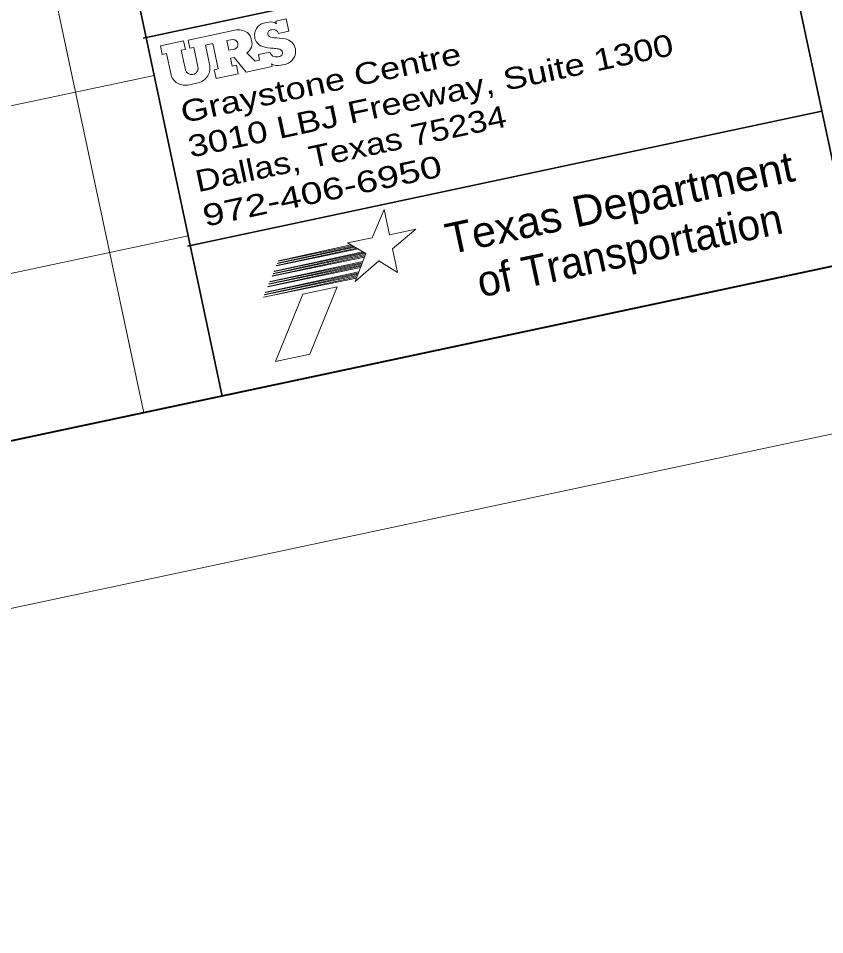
# Model space of a CAD drawing. Extents: x 2357218 to 2371708, y 6973728 to 6980157.
# Drawn here: x 2370463 to 2370955, y 6976249 to 6976808 of the extents above; entities that cross this region are included whole.
import ezdxf
from ezdxf.enums import TextEntityAlignment as Align

# ---------------------------------------------------------------- set-up
doc = ezdxf.new("R2010")
doc.units = 0
doc.header["$LTSCALE"] = 2
doc.layers.add('62', color=7, linetype='Continuous', lineweight=13)
doc.layers.add('63', color=7, linetype='Continuous', lineweight=13)

msp = doc.modelspace()

# ---------------------------------------------------------------- linework, layer by layer
at = {"layer": '62'}
for p, q in [((2370248.639, 6977936.603), (2370539.727, 6976567.134)), ((2370613.117, 6976804.817), (2370616.379, 6976805.51)), ((2370617.969, 6976800.812), (2370617.299, 6976800.67)), ((2370590.421, 6976794.162), (2370594.103, 6976794.945)), ((2370621.607, 6976784.237), (2370622.774, 6976784.526)), ((2370626.668, 6976779.864), (2370623.407, 6976779.171)), ((2370546.085, 6976772.963), (2358711.903, 6974257.531)), ((2370569.722, 6976773.59), (2370570.563, 6976773.769)), ((2370572.972, 6976768.447), (2370567.541, 6976767.296)), ((2370566.878, 6976675.145), (2358732.695, 6974159.712)), ((2371343.073, 6976635.653), (2358039.664, 6973807.926))]:
    msp.add_line(p, q, dxfattribs=at)
at = {"layer": '62', "lineweight": 35}
for p, q in [((2370463.576, 6977161.139), (2370587.67, 6976577.324)), ((2371176.22, 6976931.098), (2370539.396, 6976795.736)), ((2370972.547, 6976661.874), (2370926.598, 6976878.04)), ((2370953.581, 6976751.099), (2370566.378, 6976668.796))]:
    msp.add_line(p, q, dxfattribs=at)
at = {"layer": '62', "lineweight": 40}
msp.add_line((2371224.464, 6976712.679), (2358116.692, 6973926.537), dxfattribs=at)
at = {"layer": '62'}
for points in [[(2370620.492, 6976804.659), (2370620.728, 6976804.709), (2370620.444, 6976806.044), (2370626.757, 6976807.386), (2370628.345, 6976799.913), (2370622.032, 6976798.571)], [(2370572.786, 6976778.312), (2370570.303, 6976789.996), (2370567.988, 6976789.504), (2370566.937, 6976794.451), (2370595.344, 6976800.489)], [(2370556.215, 6976774.02), (2370553.597, 6976786.335), (2370551.072, 6976785.798), (2370549.976, 6976790.956), (2370564.074, 6976793.952), (2370565.17, 6976788.795), (2370562.645, 6976788.258), (2370565.173, 6976776.364)], [(2370617.721, 6976780.053), (2370618.079, 6976778.369), (2370602.298, 6976775.014), (2370594.912, 6976783.895), (2370592.703, 6976783.426), (2370593.732, 6976778.584), (2370596.362, 6976779.143), (2370597.458, 6976773.985), (2370583.886, 6976771.101), (2370582.768, 6976776.363), (2370585.187, 6976776.878), (2370581.899, 6976792.351), (2370577.374, 6976791.389), (2370579.836, 6976779.811)], [(2370594.724, 6976788.916), (2370591.673, 6976788.268), (2370590.421, 6976794.162)], [(2370602.61, 6976786.763), (2370607.807, 6976781.686), (2370610.438, 6976782.245), (2370609.722, 6976785.613), (2370616.666, 6976787.089)]]:
    msp.add_lwpolyline(points, dxfattribs=at)
for points in [[(2370686.385, 6976691.127), (2370679.1, 6976673.906), (2370664.09, 6976670.714), (2370675.305, 6976664.349), (2370668.728, 6976647.259), (2370683.179, 6976659.825), (2370694.543, 6976652.745), (2370691.499, 6976667.061), (2370705.7, 6976679.183), (2370689.65, 6976675.763)], [(2370620.799, 6976656.901), (2370669.709, 6976667.519), (2370670.535, 6976667.045), (2370620.756, 6976656.71)], [(2370621.442, 6976658.465), (2370667.87, 6976668.566), (2370668.711, 6976668.078), (2370621.356, 6976658.278)], [(2370622.034, 6976659.919), (2370666.192, 6976669.507), (2370667.03, 6976669.057), (2370621.977, 6976659.712)], [(2370618.242, 6976650.608), (2370674.752, 6976662.9), (2370674.425, 6976662.064), (2370618.201, 6976650.413)], [(2370618.858, 6976652.171), (2370675.11, 6976664.431), (2370675.293, 6976664.344), (2370675.013, 6976663.626), (2370618.803, 6976651.957)], [(2370619.463, 6976653.612), (2370673.474, 6976665.383), (2370674.411, 6976664.834), (2370619.399, 6976653.407)], [(2370615.598, 6976644.18), (2370672.268, 6976656.479), (2370671.959, 6976655.684), (2370615.537, 6976643.969)], [(2370616.212, 6976645.727), (2370672.865, 6976658.024), (2370672.566, 6976657.24), (2370616.17, 6976645.535)], [(2370616.824, 6976647.168), (2370673.43, 6976659.46), (2370673.119, 6976658.657), (2370616.755, 6976646.979)], [(2370612.966, 6976637.74), (2370669.807, 6976650.091), (2370669.501, 6976649.327), (2370612.885, 6976637.559)], [(2370613.573, 6976639.311), (2370670.412, 6976651.632), (2370670.115, 6976650.883), (2370613.518, 6976639.099)], [(2370614.184, 6976640.73), (2370670.959, 6976653.066), (2370670.66, 6976652.308), (2370614.118, 6976640.534)], [(2370636.881, 6976639.517), (2370620.08, 6976598.402), (2370641.016, 6976602.852), (2370657.803, 6976643.97)]]:
    msp.add_lwpolyline(points, close=True, dxfattribs=at)
for centre, radius, start, end in [((2370597.546, 6976790.537), 10.193, 57.4181, 102.47644), ((2370614.691, 6976797.617), 7.37, 102.32723, 191.15289), ((2370617.472, 6976800.429), 5.198, 54.47521, 102.13887), ((2370618.846, 6976797.598), 3.331, 16.97622, 105.26327), ((2370597.372, 6976793.059), 8.299, 9.96198, 46.96983), ((2370613.981, 6976796.942), 6.564, 186.56461, 251.65547), ((2370617.647, 6976798.529), 2.168, 99.22466, 192.15024), ((2370617.188, 6976798.198), 1.665, 184.31019, 211.43935), ((2370619.351, 6976801.357), 5.392, 228.33024, 267.8676), ((2370604.89, 6976620.593), 175.955, 83.11463, 85.35109), ((2370624.504, 6976787.405), 8.012, 12.4748, 79.35646), ((2370594.147, 6976791.848), 3.097, 3.97357, 90.82265), ((2370594.423, 6976791.733), 2.833, 276.11318, 6.67154), ((2370599.4, 6976792.405), 6.491, 299.63423, 18.78306), ((2370619.226, 6976811.978), 22.489, 251.02735, 268.92656), ((2370620.866, 6976788.659), 4.484, 200.49107, 279.52171), ((2370616.627, 6976761.895), 27.684, 78.98519, 85.48674), ((2370621.85, 6976786.4), 2.67, 8.42761, 88.58816), ((2370622.247, 6976786.709), 2.246, 283.56527, 2.09036), ((2370624.233, 6976787.713), 8.218, 287.23994, 9.97211), ((2370571.011, 6976777.386), 9.152, 282.37291, 15.36393), ((2370621.51, 6976785.711), 6.81, 236.19553, 286.17379), ((2370564.973, 6976775.872), 8.952, 191.94291, 286.66556), ((2370568.864, 6976777.3), 3.807, 194.2293, 283.01817), ((2370569.385, 6976777.161), 3.591, 289.15137, 18.69604)]:
    msp.add_arc(centre, radius, start, end, dxfattribs=at)
at = {"layer": '63'}
for p, q in [((2370248.639, 6977936.603), (2370539.727, 6976567.134)), ((2370546.085, 6976772.963), (2358711.903, 6974257.531)), ((2370566.878, 6976675.145), (2358732.695, 6974159.712)), ((2371343.073, 6976635.653), (2358039.664, 6973807.926))]:
    msp.add_line(p, q, dxfattribs=at)
at = {"layer": '63', "lineweight": 35}
msp.add_line((2370463.576, 6977161.139), (2370587.67, 6976577.324), dxfattribs=at)
at = {"layer": '63', "lineweight": 40}
msp.add_line((2371224.464, 6976712.679), (2358116.692, 6973926.537), dxfattribs=at)
at = {"layer": '63'}
for points in [[(2370686.385, 6976691.127), (2370679.1, 6976673.906), (2370664.09, 6976670.714), (2370675.305, 6976664.349), (2370668.728, 6976647.259), (2370683.179, 6976659.825), (2370694.543, 6976652.745), (2370691.499, 6976667.061), (2370705.7, 6976679.183), (2370689.65, 6976675.763)], [(2370620.799, 6976656.901), (2370669.709, 6976667.519), (2370670.535, 6976667.045), (2370620.756, 6976656.71)], [(2370621.442, 6976658.465), (2370667.87, 6976668.566), (2370668.711, 6976668.078), (2370621.356, 6976658.278)], [(2370622.034, 6976659.919), (2370666.192, 6976669.507), (2370667.03, 6976669.057), (2370621.977, 6976659.712)], [(2370618.242, 6976650.608), (2370674.752, 6976662.9), (2370674.425, 6976662.064), (2370618.201, 6976650.413)], [(2370618.858, 6976652.171), (2370675.11, 6976664.431), (2370675.293, 6976664.344), (2370675.013, 6976663.626), (2370618.803, 6976651.957)], [(2370619.463, 6976653.612), (2370673.474, 6976665.383), (2370674.411, 6976664.834), (2370619.399, 6976653.407)], [(2370615.598, 6976644.18), (2370672.268, 6976656.479), (2370671.959, 6976655.684), (2370615.537, 6976643.969)], [(2370616.212, 6976645.727), (2370672.865, 6976658.024), (2370672.566, 6976657.24), (2370616.17, 6976645.535)], [(2370616.824, 6976647.168), (2370673.43, 6976659.46), (2370673.119, 6976658.657), (2370616.755, 6976646.979)], [(2370612.966, 6976637.74), (2370669.807, 6976650.091), (2370669.501, 6976649.327), (2370612.885, 6976637.559)], [(2370613.573, 6976639.311), (2370670.412, 6976651.632), (2370670.115, 6976650.883), (2370613.518, 6976639.099)], [(2370614.184, 6976640.73), (2370670.959, 6976653.066), (2370670.66, 6976652.308), (2370614.118, 6976640.534)], [(2370636.881, 6976639.517), (2370620.08, 6976598.402), (2370641.016, 6976602.852), (2370657.803, 6976643.97)]]:
    msp.add_lwpolyline(points, close=True, dxfattribs=at)

# ---------------------------------------------------------------- texts
at = {"layer": '62'}
for s, width, p in [('3010 LBJ Freeway, Suite 1300', 1.25, (2370568.378, 6976722.731)), ('Graystone Centre', 1.25, (2370563.898, 6976743.809)), ('Dallas, Texas 75234', 1.2, (2370572.858, 6976701.654)), ('972-406-6950', 1.35, (2370577.339, 6976680.576))]:
    msp.add_text(s, height=13.22, rotation=12, dxfattribs=dict(at, width=width)).set_placement(p)
at = {"layer": '62', "width": 1.05}
msp.add_text('Texas Department', height=18.76, rotation=12, dxfattribs=at).set_placement((2370832.096, 6976686.184), align=Align.CENTER)
at = {"layer": '62'}
msp.add_text('of Transportation', height=18.76, rotation=12, dxfattribs=at).set_placement((2370838.193, 6976657.165), align=Align.CENTER)
at = {"layer": '63', "width": 1.05}
msp.add_text('Texas Department', height=18.76, rotation=12, dxfattribs=at).set_placement((2370832.096, 6976686.184), align=Align.CENTER)
at = {"layer": '63'}
msp.add_text('of Transportation', height=18.76, rotation=12, dxfattribs=at).set_placement((2370838.193, 6976657.165), align=Align.CENTER)

doc.saveas('drawing.dxf')
